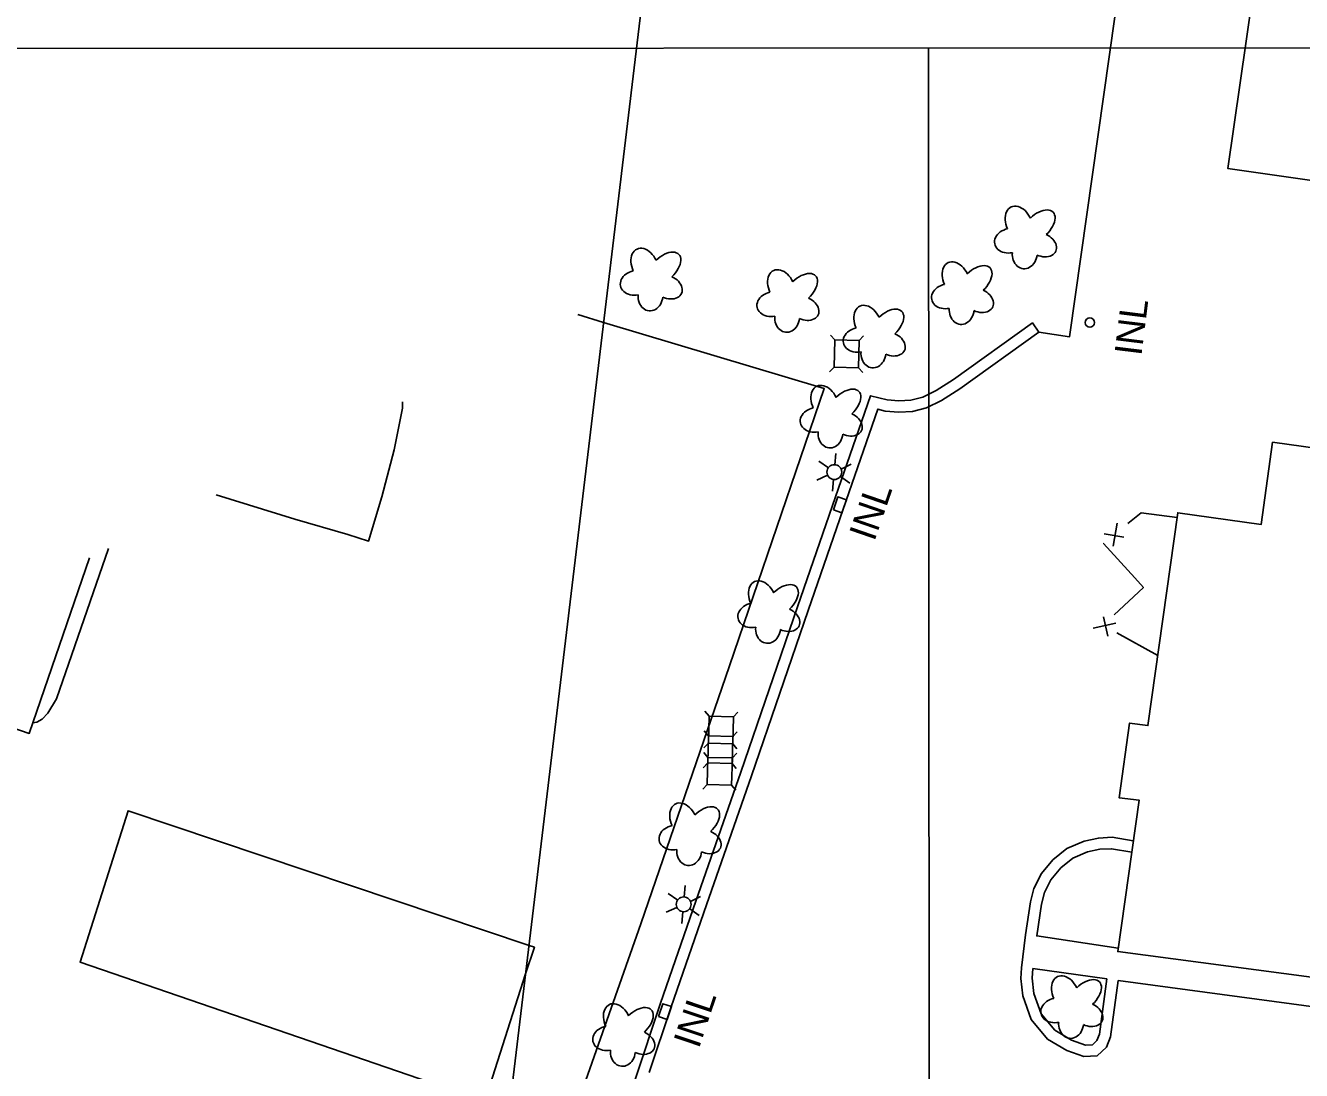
# Model space of a CAD drawing. Extents: x 189384 to 193282, y 256970 to 260388.
# Drawn here: x 190446.7 to 190728.8, y 259285.3 to 259516.4 of the extents above; entities that cross this region are included whole.
import ezdxf

# ---------------------------------------------------------------- set-up
doc = ezdxf.new("R2010")
doc.units = 0
for name, color, linetype in [('E_DWY', 7, 'Continuous'), ('E_LAND_Vegetation', 7, 'Continuous'), ('E_MAP_GridLines', 7, 'Continuous'), ('E_MAP_Limits', 7, 'Continuous'), ('E_MISCPROP', 7, 'Continuous'), ('E_MISCPROP_HvyLine', 7, 'Continuous'), ('E_MISCPROP_Railing', 7, 'Continuous'), ('E_PATH_Sidewalk', 7, 'Continuous'), ('E_UTL_AboveGroundPipe', 7, 'Continuous')]:
    doc.layers.add(name, color=color, linetype=linetype)

# ---------------------------------------------------------------- blocks, each defined once
blk = doc.blocks.new('INL_4')
at = {"layer": 'E_MISCPROP_Railing'}
blk.add_text('INL', height=6, rotation=360, dxfattribs=at).set_placement((-5.79, -2.75))
blk = doc.blocks.new('INLT')
at = {"layer": 'E_MISCPROP_Railing'}
blk.add_lwpolyline([(3, -2), (3, 0), (0, 0), (0, -2), (3, -2)], dxfattribs=at)
blk = doc.blocks.new('INL_9')
at = {"layer": 'E_MISCPROP_Railing'}
blk.add_text('INL', height=6, rotation=0, dxfattribs=at).set_placement((-5.79, -2.75))
blk = doc.blocks.new('INL_10')
at = {"layer": 'E_MISCPROP_Railing'}
blk.add_text('INL', height=6, rotation=360, dxfattribs=at).set_placement((-5.79, -2.75))
blk = doc.blocks.new('PED')
at = {"layer": 'E_UTL_AboveGroundPipe'}
for p, q in [((-2.34, 2.71), (-3.29, 3.77)), ((3.06, 2.71), (4.02, 3.77)), ((-3.29, -4.35), (-2.34, -3.29)), ((4.02, -4.35), (3.06, -3.29))]:
    blk.add_line(p, q, dxfattribs=at)
blk.add_lwpolyline([(-2.34, -3.29), (3.06, -3.29), (3.06, 2.71), (-2.34, 2.71)], close=True, dxfattribs=at)
blk = doc.blocks.new('LTP_1')
at = {"layer": 'E_MISCPROP'}
for p, q in [((-0.78, 1.46), (-1.98, 3.76)), ((0.86, 1.37), (2.22, 3.6)), ((-1.61, 0.09), (-4.22, 0.17)), ((1.66, 0), (4.18, -0.07)), ((-0.86, -1.4), (-2.22, -3.59)), ((0.78, -1.44), (2.02, -3.62))]:
    blk.add_line(p, q, dxfattribs=at)
blk.add_circle((0.02, 0.01), 1.64, dxfattribs=at)
blk = doc.blocks.new('TREE')
at = {"layer": 'E_LAND_Vegetation'}
for centre, major_axis, ratio in [((-1.07, 3.38), (0.91, -3.32), 0.782863), ((2.88, 1.66), (-3.52, -1.95), 0.691916), ((-3.74, -0.07), (3.29, -0.08), 0.832022), ((-1.48, -3.66), (1.2, 3.24), 0.716896), ((2.54, -2.64), (-3.34, 3.06), 0.560249)]:
    blk.add_ellipse(centre, major_axis=major_axis, ratio=ratio, start_param=1.570796, end_param=4.712389, dxfattribs=at)

msp = doc.modelspace()

# ---------------------------------------------------------------- linework, layer by layer
at = {"layer": 'E_DWY'}
for points in [[(190670.76, 259448.61), (190677.52, 259447.58), (190692.62, 259554.31), (190721.93, 259550.33)], [(190566.32, 259247.73), (190562.88, 259258.82), (190570.05, 259281.71), (190582.74, 259317.74), (190602.32, 259374.81), (190623.28, 259436.15), (190574.48, 259450.72)], [(190566.32, 259247.73), (190562.88, 259258.82), (190570.05, 259281.71), (190582.74, 259317.74), (190602.32, 259374.81), (190623.28, 259436.15), (190574.48, 259450.72)], [(190574.48, 259450.72), (190568.8, 259452.52)], [(190581.44, 259283.34), (190587.1, 259300.2), (190594.85, 259322.79), (190604.81, 259351.29), (190617.36, 259387.87), (190625.75, 259412.18), (190633.52, 259434.55), (190637.18, 259433.64), (190639.78, 259433.42), (190642.39, 259433.55), (190645.04, 259434.21), (190648.02, 259435.69), (190651.88, 259438.11), (190669.3, 259450.64), (190670.76, 259448.61)], [(190581.44, 259283.34), (190587.1, 259300.2), (190594.85, 259322.79), (190604.81, 259351.29), (190617.36, 259387.87), (190625.75, 259412.18), (190633.52, 259434.55), (190637.18, 259433.64), (190639.78, 259433.42), (190642.39, 259433.55), (190645.04, 259434.21), (190648.02, 259435.69), (190651.88, 259438.11), (190669.3, 259450.64), (190670.76, 259448.61)], [(190584.59, 259284.87), (190589.46, 259299.4), (190597.21, 259321.97), (190607.17, 259350.47), (190619.72, 259387.06), (190628.12, 259411.36), (190635.13, 259431.57), (190636.77, 259431.16), (190639.74, 259430.91), (190642.76, 259431.07), (190645.91, 259431.85), (190649.24, 259433.5), (190653.27, 259436.04), (190670.76, 259448.61)], [(190584.59, 259284.87), (190589.46, 259299.4), (190597.21, 259321.97), (190607.17, 259350.47), (190619.72, 259387.06), (190628.12, 259411.36), (190635.13, 259431.57), (190636.77, 259431.16), (190639.74, 259430.91), (190642.76, 259431.07), (190645.91, 259431.85), (190649.24, 259433.5), (190653.27, 259436.04), (190670.76, 259448.61)], [(190530.05, 259433.21), (190529.99, 259431.8), (190528.21, 259422.61), (190525.45, 259412.15), (190522.53, 259402.39), (190517.92, 259403.85), (190506.2, 259407.24), (190488.84, 259412.66)], [(190465, 259400.78), (190453.49, 259367.48), (190451.57, 259364.33), (190450.37, 259362.99), (190449.19, 259362.38), (190448.29, 259362.18)], [(190850.91, 259385.28), (190857.2, 259384.55), (190843.24, 259284.34), (190688.25, 259305.24)], [(190691.62, 259336.1), (190686.94, 259336.88), (190683.9, 259336.73), (190680.72, 259336.05), (190676.93, 259334.41), (190673.81, 259331.89), (190671.3, 259328.85), (190669.61, 259325.57), (190668.86, 259322.59), (190667.76, 259315.3), (190666.87, 259308.05)], [(190691.27, 259333.62), (190686.8, 259334.37), (190684.23, 259334.24), (190681.48, 259333.66), (190678.24, 259332.25), (190675.58, 259330.1), (190673.4, 259327.47), (190671.97, 259324.68), (190671.31, 259322.09), (190670.25, 259315.06), (190688.26, 259312.36)], [(190666.87, 259308.05), (190666.73, 259305.69), (190667.16, 259301.8), (190669.06, 259296.58), (190672.63, 259292.27), (190676.89, 259289.75), (190680.66, 259288.4), (190683.64, 259288.57), (190685.68, 259290.49), (190686.58, 259292.74), (190688.25, 259305.24)], [(190669.37, 259307.9), (190669.24, 259305.75), (190669.61, 259302.37), (190671.26, 259297.84), (190674.28, 259294.2), (190677.96, 259292.02), (190681.02, 259290.93), (190682.59, 259291.02), (190683.56, 259291.93), (190684.14, 259293.38), (190685.77, 259305.57)]]:
    msp.add_lwpolyline(points, dxfattribs=at)
at = {"layer": 'E_MAP_GridLines'}
for p, q in [((190146.34, 259511.09), (191646.33, 259512.15)), ((190146.34, 259511.09), (191646.33, 259512.15)), ((190146.34, 259511.09), (191646.33, 259512.15)), ((190647.05, 258511.45), (190646.34, 259511.44))]:
    msp.add_line(p, q, dxfattribs=at)
at = {"layer": 'E_MAP_Limits'}
msp.add_lwpolyline([(190622.49, 259989.85), (190597.72, 259644.89), (190538.23, 259147.8)], dxfattribs=at)
at = {"layer": 'E_MISCPROP_HvyLine'}
msp.add_lwpolyline([(190862.07, 259463.38), (190862.07, 259463.38), (190712.55, 259484.77), (190712.55, 259484.77), (190722.01, 259550.92), (190871.53, 259529.52), (190871.53, 259529.52), (190871.53, 259529.52)], close=True, dxfattribs=at)
for points in [[(190749.79, 259420.44), (190722.43, 259424.27), (190719.89, 259406.09), (190719.89, 259406.09), (190719.89, 259406.09), (190701.44, 259408.67), (190701.44, 259408.67), (190694.85, 259361.59), (190694.85, 259361.59), (190690.81, 259362.16), (190690.81, 259362.16), (190688.49, 259345.6), (190688.49, 259345.6), (190688.49, 259345.6), (190692.9, 259345.13), (190688.16, 259311.6), (190688.16, 259311.6), (190822.79, 259293.76)], [(190396.05, 259410.47), (190386.05, 259381.33), (190386.05, 259381.33), (190404.91, 259374.85), (190398.92, 259357.41), (190398.92, 259357.41), (190380.31, 259363.8), (190380.31, 259363.8), (190366.46, 259323.45), (190366.46, 259323.45), (190366.46, 259323.45), (190428.13, 259302.28), (190428.13, 259302.28), (190442.05, 259342.85), (190442.05, 259342.85), (190422.58, 259349.53), (190428.37, 259366.41), (190428.37, 259366.41), (190428.37, 259366.41), (190447.49, 259359.85), (190460.82, 259398.7)], [(190558, 259312.97), (190469.33, 259342.75), (190458.71, 259309.27), (190548.23, 259278.56), (190557.24, 259306.69)], [(190557.24, 259306.69), (190559.2, 259312.57), (190559.2, 259312.57), (190559.2, 259312.57), (190558, 259312.97)], [(190557.24, 259306.69), (190559.2, 259312.57), (190559.2, 259312.57), (190559.2, 259312.57), (190558, 259312.97)]]:
    msp.add_lwpolyline(points, dxfattribs=at)
at = {"layer": 'E_MISCPROP_Railing'}
for p, q in [((190687.18, 259401.29), (190688.06, 259406.34)), ((190685.19, 259404.02), (190689.53, 259403.29)), ((190687.75, 259384.24), (190682.74, 259383.15)), ((190685.97, 259381.37), (190685.01, 259385.66))]:
    msp.add_line(p, q, dxfattribs=at)
for points in [[(190690.42, 259406.25), (190693.36, 259408.63), (190701.29, 259407.61)], [(190691.95, 259394.27), (190685.04, 259401.88), (190685.1, 259401.93)], [(190687.37, 259386.05), (190693.87, 259392.14), (190691.95, 259394.27)], [(190697.02, 259377.09), (190687.94, 259382.07)]]:
    msp.add_lwpolyline(points, dxfattribs=at)
msp.add_circle((190682.01, 259450.72), 1.02, dxfattribs=at)
at = {"layer": 'E_PATH_Sidewalk'}
msp.add_lwpolyline([(190685.77, 259305.57), (190669.37, 259307.9)], dxfattribs=at)

# ---------------------------------------------------------------- block references
at = {"layer": 'E_LAND_Vegetation'}
for p, rotation in [((190667.79, 259469.65), 86.03298006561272), ((190667.79, 259469.65), 86.03298006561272), ((190585.03, 259460.33), 86.03298154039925), ((190585.03, 259460.33), 86.03298154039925), ((190653.85, 259457.34), 86.03298031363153), ((190653.85, 259457.34), 86.03298031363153), ((190615.25, 259455.6), 86.03298100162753), ((190615.25, 259455.6), 86.03298100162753), ((190634.33, 259447.72), 86.03298066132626), ((190634.33, 259447.72), 86.03298066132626), ((190624.83, 259430.02), 86.03298083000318), ((190624.83, 259430.02), 86.03298083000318), ((190611.03, 259386.81), 86.03298107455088), ((190611.03, 259386.81), 86.03298107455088), ((190593.6, 259337.66), 86.03298138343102), ((190593.6, 259337.66), 86.03298138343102), ((190678.04, 259299.44), 86.03297987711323), ((190578.94, 259293.27), 86.03298164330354), ((190578.94, 259293.27), 86.03298164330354)]:
    msp.add_blockref('TREE', p, dxfattribs=dict(at, rotation=rotation))
at = {"layer": 'E_MISCPROP'}
for p, xscale, yscale, rotation in [((190625.52, 259417.63), 1.000001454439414, 1.000001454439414, 86.2723249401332), ((190625.52, 259417.63), 1.000001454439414, 1.000001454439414, 86.2723249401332), ((190592.2, 259322.03), 1.0000014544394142, 1.0000014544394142, 86.27232553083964), ((190592.2, 259322.03), 1.0000014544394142, 1.0000014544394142, 86.27232553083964)]:
    msp.add_blockref('LTP_1', p, dxfattribs=dict(at, xscale=xscale, yscale=yscale, rotation=rotation))
at = {"layer": 'E_MISCPROP_Railing'}
for name, p, xscale, yscale, rotation in [('INL_4', (190691.38, 259449.29), 0.9999984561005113, 0.9999984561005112, 82.9299962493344), ('INL_9', (190594.76, 259296.33), 1.0000024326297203, 1.00000243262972, 71.45170790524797), ('INL_9', (190594.76, 259296.33), 1.0000024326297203, 1.00000243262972, 71.45170790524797), ('INLT', (190589.48, 259299.44), 1.0000024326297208, 1.0000024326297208, -108.54829200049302), ('INLT', (190589.48, 259299.44), 1.0000024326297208, 1.0000024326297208, -108.54829200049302)]:
    msp.add_blockref(name, p, dxfattribs=dict(at, xscale=xscale, yscale=yscale, rotation=rotation))
for name, p, rotation in [('INL_10', (190633.62, 259408.5), 70.94900968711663), ('INL_10', (190633.62, 259408.5), 70.94900968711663), ('INLT', (190628.17, 259411.51), -109.05099021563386), ('INLT', (190628.17, 259411.51), -109.05099021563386)]:
    msp.add_blockref(name, p, dxfattribs=dict(at, rotation=rotation))
at = {"layer": 'E_UTL_AboveGroundPipe'}
for p, xscale, yscale, rotation in [((190628.58, 259443.51), 0.9999978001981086, 0.9999978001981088, 178.52108312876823), ((190628.58, 259443.51), 0.9999978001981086, 0.9999978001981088, 178.52108312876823), ((190600.78, 259360.33), 0.9999978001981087, 0.9999978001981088, 178.52108362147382), ((190600.78, 259360.33), 0.9999978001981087, 0.9999978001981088, 178.52108362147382), ((190600.64, 259355.95), 0.9999978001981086, 0.9999978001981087, 178.52108362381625), ((190600.64, 259355.95), 0.9999978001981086, 0.9999978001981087, 178.52108362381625), ((190600.53, 259351.2), 0.9999978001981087, 0.9999978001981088, 178.52108362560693), ((190600.53, 259351.2), 0.9999978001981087, 0.9999978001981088, 178.52108362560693)]:
    msp.add_blockref('PED', p, dxfattribs=dict(at, xscale=xscale, yscale=yscale, rotation=rotation))

doc.saveas('drawing.dxf')
